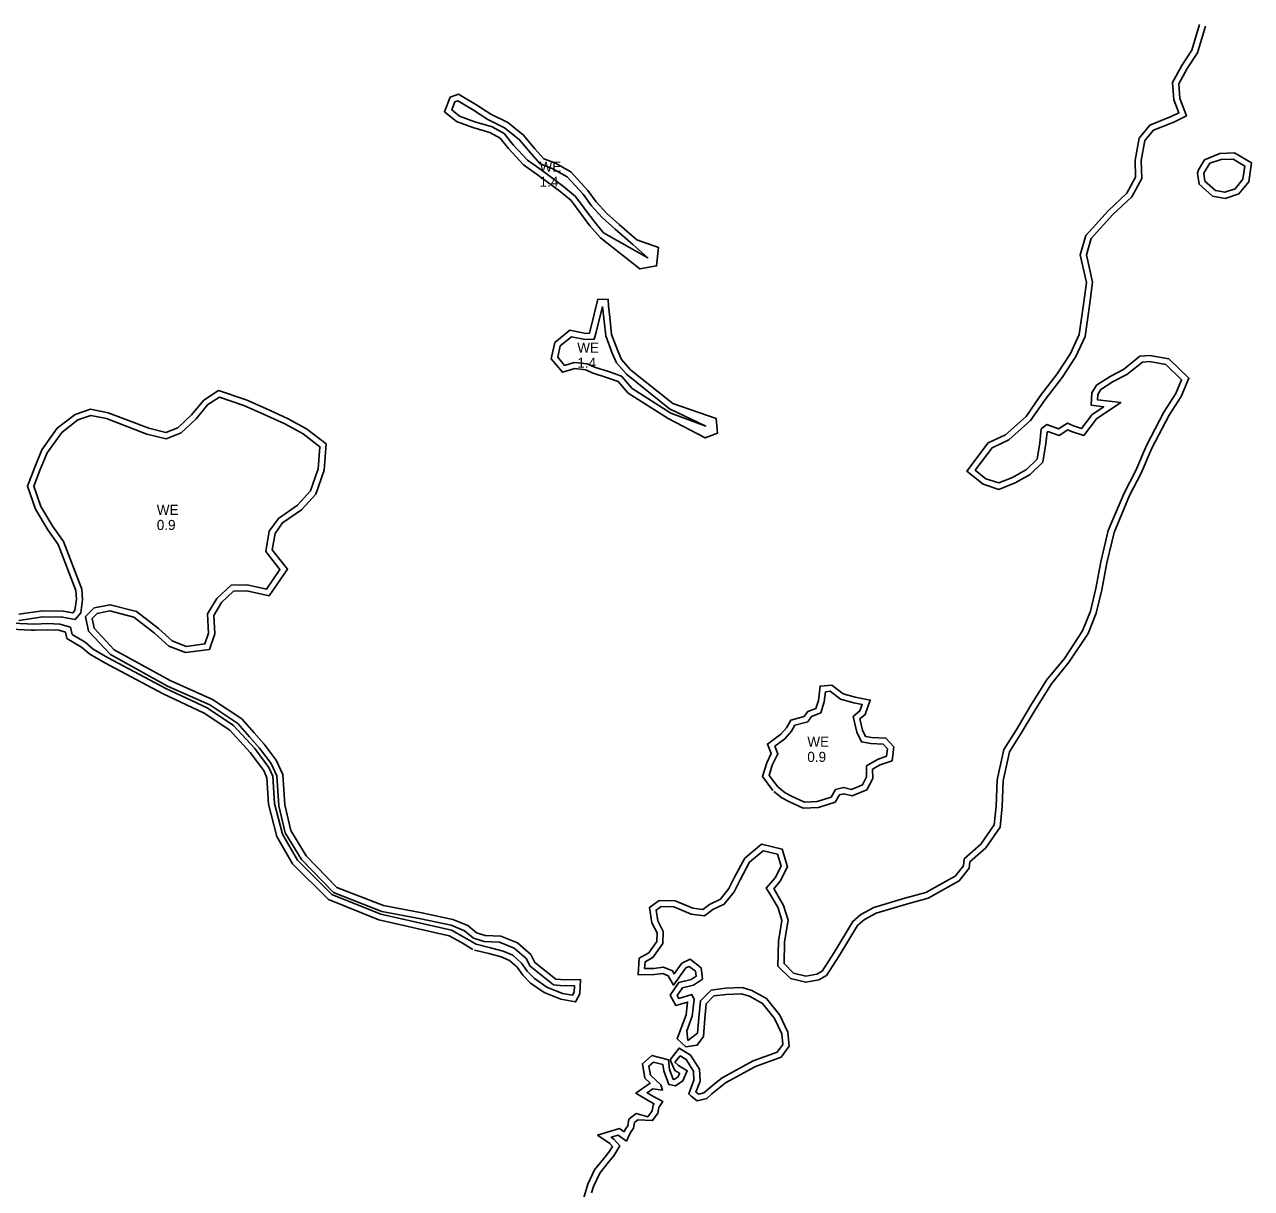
# Model space of a CAD drawing. Extents: x 2160437 to 2172832, y 205694 to 212444.
# Drawn here: x 2167169 to 2167777, y 209235 to 209811 of the extents above; entities that cross this region are included whole.
import ezdxf

# ---------------------------------------------------------------- set-up
doc = ezdxf.new("R2010")
doc.units = 0
for name, color, linetype in [('RD_EX_H2O', 7, 'Continuous'), ('RD_EX_H2O_Pond', 7, 'Continuous'), ('RD_EX_H2O_txCode', 7, 'Continuous'), ('RD_EX_VEG_ShrubLine', 7, 'Continuous')]:
    doc.layers.add(name, color=color, linetype=linetype)

msp = doc.modelspace()

# ---------------------------------------------------------------- linework, layer by layer
at = {"layer": 'RD_EX_H2O'}
for points in [[(2167645.06, 209403.52), (2167652.09, 209413.78), (2167653.08, 209423.92), (2167653.67, 209436.74), (2167656.69, 209451.07), (2167662.59, 209460.23), (2167669.71, 209472.32), (2167677.57, 209484.7), (2167686.36, 209495.54), (2167695.63, 209509.64), (2167699.72, 209519.75), (2167702.49, 209531.33), (2167704.89, 209544.57), (2167708.54, 209559.73), (2167716.18, 209577.94), (2167722.01, 209589.13), (2167727.24, 209601.46), (2167735.77, 209617.77), (2167741.77, 209627.13), (2167745.6, 209636.11), (2167735.59, 209645.64), (2167726.18, 209647.42), (2167721.38, 209646.99), (2167713.19, 209640.49), (2167706.62, 209636.99), (2167699.77, 209632.62), (2167697.48, 209628.93), (2167697.25, 209622.68), (2167703.42, 209621.99), (2167697.67, 209618.12), (2167692.4, 209611.17), (2167688.49, 209612.45), (2167685.39, 209613.86), (2167681.03, 209611.1), (2167675.22, 209613.12), (2167672.5, 209610.99), (2167671.74, 209604.11), (2167670.42, 209595.99), (2167665.13, 209590.91), (2167658.22, 209586.95), (2167651.37, 209584.21), (2167645.09, 209586.31), (2167639.8, 209590.58), (2167648.07, 209601.65), (2167656.46, 209605.57), (2167667.17, 209615.16), (2167674.59, 209625.74), (2167682.83, 209636.46), (2167689.65, 209646.82), (2167694.2, 209656.84), (2167696.58, 209673.33), (2167697.92, 209683.68), (2167694.83, 209697.18), (2167697.27, 209705.29), (2167707.89, 209717.16), (2167717.26, 209725.99), (2167722.21, 209734.96), (2167722.02, 209743.89), (2167723.79, 209753.8), (2167728.01, 209758.99), (2167738.07, 209763.02), (2167744.45, 209766.1), (2167741.09, 209774.61), (2167740.56, 209781.95), (2167744.75, 209789.52), (2167749.89, 209797.28), (2167753.76, 209810.47)], [(2167645.06, 209403.52), (2167637.12, 209396.47), (2167636.78, 209393.38), (2167631.81, 209387.1), (2167616.41, 209378.58), (2167605.78, 209375.62), (2167590.7, 209371.07), (2167584.87, 209367.99), (2167581.48, 209365.04), (2167572.42, 209350.03), (2167566, 209340.17), (2167562.35, 209338.03), (2167555.77, 209336.84), (2167548.16, 209338.74), (2167542.04, 209344.89), (2167542.34, 209357.21), (2167543.99, 209367.43), (2167542.06, 209373.73), (2167537.53, 209381.46), (2167536.26, 209383.46), (2167540.61, 209388.65), (2167543.57, 209394.35), (2167541.73, 209400.3), (2167534.63, 209401.96), (2167527.91, 209396.35), (2167523.24, 209387.57), (2167520.31, 209381.68), (2167515.43, 209375.6), (2167509.69, 209372.85), (2167505.59, 209369.85), (2167499.11, 209370.68), (2167490.43, 209374.19), (2167484.17, 209374.41), (2167481.68, 209372.62), (2167482.48, 209367.27), (2167485.2, 209361.99), (2167484.94, 209356.06), (2167480.06, 209349.18), (2167476.21, 209347), (2167475.98, 209343.62), (2167480.6, 209343.64), (2167485.4, 209344.32), (2167489.78, 209342.46), (2167490.57, 209341.04), (2167494.41, 209346.33), (2167498.53, 209348.26), (2167503.94, 209344), (2167504.71, 209338.42), (2167500.25, 209335.46), (2167494.74, 209334.16), (2167492.17, 209330.28), (2167492.91, 209328.89), (2167499.41, 209330.86), (2167500.46, 209328.38), (2167499.45, 209320.12), (2167496.85, 209312.89), (2167497.39, 209308.03), (2167502.18, 209311.59), (2167502.79, 209319.23), (2167503.61, 209327.64), (2167508.95, 209332.94), (2167516.1, 209333.87), (2167524.29, 209334.2), (2167529.04, 209332.85), (2167536.4, 209328.76), (2167542.9, 209320.57), (2167546.87, 209312.17), (2167547.58, 209305.24), (2167543.58, 209299.71), (2167530.98, 209295.15), (2167516.1, 209287.08), (2167513.34, 209284.84), (2167509.34, 209281.67), (2167506.79, 209279.34), (2167502.08, 209278.18), (2167499.03, 209280.5), (2167497.84, 209281.6), (2167500.43, 209288.4), (2167500.14, 209292.83), (2167496.6, 209298.61), (2167493.66, 209300.38), (2167490.99, 209297.24), (2167492.73, 209295.57), (2167497.06, 209293.04), (2167494.96, 209288.02), (2167491.22, 209285.54), (2167487.89, 209286.3), (2167485.44, 209292.97), (2167485.06, 209296.13), (2167480.32, 209297.34), (2167478.11, 209295.36), (2167478.92, 209290.82), (2167483.99, 209286.08), (2167484.8, 209283.35), (2167480.03, 209284.08), (2167477.21, 209282.12), (2167480.06, 209280.45), (2167484.94, 209277.74), (2167483.09, 209274.9), (2167482.59, 209272.02), (2167479.93, 209268.36), (2167472.68, 209268.73), (2167470.88, 209267.37), (2167470.45, 209264.63), (2167468.98, 209262.5), (2167467.88, 209259.94), (2167466.96, 209258.18), (2167462.94, 209261.13), (2167459.47, 209260.08), (2167460.75, 209259.19), (2167463.75, 209255.78), (2167460.73, 209250.92), (2167458.11, 209247.75), (2167453.74, 209242.38), (2167450.66, 209235.74), (2167449.71, 209232.56)]]:
    msp.add_lwpolyline(points, dxfattribs=at)
msp.add_lwpolyline([(2167753.34, 209744.24), (2167760.99, 209747.37), (2167768.24, 209747.69), (2167776.6, 209742.78), (2167775.22, 209733.43), (2167770.37, 209727.41), (2167763.6, 209725.13), (2167757.36, 209726.22), (2167750.74, 209732.21), (2167749.88, 209737.72), (2167750.33, 209739.26)], close=True, dxfattribs=at)
at = {"layer": 'RD_EX_H2O_Pond'}
for points in [[(2167455.63, 209708.17), (2167451.3, 209713.44), (2167446.57, 209719.64), (2167441.76, 209726.19), (2167435.79, 209731.14), (2167425.16, 209739.02), (2167417.96, 209744.16), (2167410.77, 209751.79), (2167406.35, 209757.41), (2167400.39, 209760.62), (2167391.81, 209763.14), (2167384.32, 209765.98), (2167380.42, 209769.06), (2167381.97, 209773.03), (2167383.45, 209773.54), (2167390.77, 209769.22), (2167398.32, 209764.3), (2167406.62, 209760.22), (2167413.87, 209754.37), (2167419.38, 209747.69), (2167424.27, 209742.29), (2167430.15, 209740), (2167437.59, 209735.93), (2167445.48, 209727.24), (2167449.6, 209721.5), (2167454.94, 209715.71), (2167461.36, 209709.93), (2167470.07, 209702.36), (2167477.55, 209695.66)], [(2167455.12, 209671.65), (2167455.87, 209664.39), (2167456.7, 209657.03), (2167459.94, 209648.52), (2167462.02, 209643.77), (2167466.93, 209638.12), (2167488.26, 209621.01), (2167506.22, 209612.42), (2167489.02, 209618.86), (2167469.76, 209631.04), (2167464.55, 209637.14), (2167458.51, 209639.2), (2167451.08, 209641.64), (2167447.57, 209643.23), (2167441.15, 209643.91), (2167436.33, 209642.48), (2167432.95, 209646.57), (2167434.14, 209652.07), (2167439.71, 209656.65), (2167446.51, 209655.3), (2167450.98, 209655.39), (2167451.91, 209658.96)], [(2167541.95, 209433.72), (2167537.65, 209439.34), (2167539.24, 209444.48), (2167542.03, 209450.07), (2167540.49, 209453.82), (2167545.46, 209457.48), (2167548.72, 209461.24), (2167550.38, 209464.22), (2167556.77, 209465.93), (2167558.7, 209468.54), (2167563.23, 209470.28), (2167564.98, 209475.78), (2167565.58, 209480.8), (2167567.86, 209481.02), (2167572.93, 209477.09), (2167579.63, 209475.24), (2167583.75, 209474.42), (2167582.62, 209471.26), (2167579.29, 209468.6), (2167581.13, 209460.72), (2167583.37, 209455.9), (2167588.12, 209455.11), (2167594.12, 209454.88), (2167596.22, 209452.5), (2167595.79, 209448.82), (2167591.36, 209447.29), (2167585.92, 209444.09), (2167585.97, 209438.58), (2167583.91, 209434.6), (2167578.48, 209432.39), (2167574.56, 209433.36), (2167570.54, 209432.32), (2167568.34, 209428.58), (2167561.49, 209426.4), (2167555.13, 209426.11), (2167548.7, 209429.09), (2167545.54, 209430.78)]]:
    msp.add_lwpolyline(points, close=True, dxfattribs=at)
msp.add_lwpolyline([(2167159.25, 209514.89), (2167173.72, 209514.24), (2167180.33, 209514.54), (2167186.33, 209514.3), (2167191.52, 209512.7), (2167192.42, 209509.18), (2167198.78, 209505.35), (2167202.82, 209501.9), (2167209.95, 209497.72), (2167238.73, 209482.47), (2167259.25, 209472.77), (2167272.37, 209464.07), (2167282.9, 209452.69), (2167289.88, 209443.22), (2167291.84, 209438.91), (2167292.67, 209425.51), (2167296.57, 209410.22), (2167304, 209397.37), (2167321.01, 209380.36), (2167345.24, 209370.6), (2167380.22, 209362.69), (2167386.75, 209359.1), (2167392.46, 209355.76), (2167399.56, 209353.97), (2167405.92, 209352.32), (2167410.69, 209350.22), (2167415.05, 209346.37), (2167417.86, 209342.41), (2167421.45, 209338.79), (2167427.6, 209334.5), (2167435.34, 209331.36), (2167440.22, 209330.45), (2167441.08, 209331.93), (2167441.18, 209335.18), (2167434.12, 209335.28), (2167430.89, 209335.56), (2167419.19, 209344.8), (2167417.22, 209348.68), (2167411.37, 209353.77), (2167404.15, 209356.68), (2167396.42, 209357.07), (2167391.18, 209358.71), (2167386.75, 209362.4), (2167380.13, 209365.1), (2167365.03, 209368.34), (2167345.8, 209371.97), (2167321.87, 209381.28), (2167305.97, 209397.72), (2167297.97, 209410.83), (2167294.69, 209424.34), (2167293.79, 209439.08), (2167290.89, 209445.32), (2167285.12, 209452.92), (2167280.27, 209458.43), (2167274.41, 209465.14), (2167260.54, 209474.37), (2167239.68, 209483.6), (2167211.37, 209499.19), (2167200.53, 209510.85), (2167199.01, 209518.08), (2167203.35, 209522.4), (2167211.19, 209523.89), (2167224.31, 209520.55), (2167235.11, 209512.09), (2167241.92, 209505.95), (2167248.85, 209503.23), (2167258.14, 209504.49), (2167259.97, 209509.89), (2167259.49, 209519.4), (2167264.03, 209526.93), (2167271.07, 209533.51), (2167279.14, 209533.71), (2167288.59, 209531.6), (2167295.33, 209541.37), (2167288.25, 209550.2), (2167290.05, 209560.34), (2167294.52, 209566.6), (2167303.94, 209573.23), (2167310.43, 209580.25), (2167314.21, 209591.18), (2167315.1, 209602.18), (2167306.84, 209608.55), (2167297.77, 209613.54), (2167287.13, 209618.37), (2167277.47, 209622.63), (2167265.34, 209626.65), (2167259.63, 209623.01), (2167253.75, 209615.96), (2167246.35, 209608.98), (2167238.94, 209606.11), (2167229.41, 209608.45), (2167209.32, 209616.08), (2167201.62, 209617.65), (2167195.25, 209615.43), (2167187.19, 209609.19), (2167180.05, 209599.09), (2167176.59, 209590.94), (2167173.38, 209582.62), (2167176.88, 209572.5), (2167182.83, 209562.69), (2167188.06, 209555.14), (2167197.14, 209531.64), (2167197.5, 209526.55), (2167196.64, 209519.84), (2167193.82, 209516.51), (2167187.65, 209517.76), (2167177.92, 209517.88), (2167165.93, 209516.16)], dxfattribs=at)
at = {"layer": 'RD_EX_VEG_ShrubLine'}
for points in [[(2167750.89, 209811.31), (2167747.14, 209798.56), (2167742.18, 209791.08), (2167737.5, 209782.62), (2167738.13, 209773.93), (2167740.64, 209767.59), (2167736.86, 209765.77), (2167726.18, 209761.48), (2167720.97, 209755.09), (2167719.02, 209744.12), (2167719.19, 209735.7), (2167714.86, 209727.85), (2167705.74, 209719.26), (2167694.59, 209706.79), (2167691.73, 209697.28), (2167694.88, 209683.54), (2167693.61, 209673.73), (2167691.29, 209657.69), (2167687.01, 209648.27), (2167680.38, 209638.2), (2167672.17, 209627.52), (2167664.91, 209617.16), (2167654.79, 209608.1), (2167646.12, 209604.05), (2167635.67, 209590.06), (2167643.63, 209583.63), (2167651.46, 209581.01), (2167659.53, 209584.24), (2167666.94, 209588.49), (2167673.22, 209594.51), (2167674.72, 209603.7), (2167675.35, 209609.41), (2167675.78, 209609.75), (2167681.41, 209607.8), (2167685.63, 209610.46), (2167687.4, 209609.65), (2167693.5, 209607.66), (2167699.76, 209615.91), (2167711.88, 209624.07), (2167700.35, 209625.35), (2167700.44, 209628.02), (2167701.96, 209630.46), (2167708.13, 209634.4), (2167714.84, 209637.96), (2167722.54, 209644.08), (2167726.04, 209644.39), (2167734.16, 209642.85), (2167742.02, 209635.37), (2167739.11, 209628.54), (2167733.17, 209619.28), (2167724.52, 209602.74), (2167719.3, 209590.41), (2167713.47, 209579.22), (2167705.68, 209560.67), (2167701.95, 209545.19), (2167699.55, 209531.94), (2167696.86, 209520.67), (2167692.96, 209511.04), (2167683.93, 209497.31), (2167675.13, 209486.46), (2167667.15, 209473.89), (2167660.04, 209461.8), (2167653.87, 209452.23), (2167650.68, 209437.12), (2167650.09, 209424.14), (2167649.18, 209414.84), (2167642.58, 209405.21), (2167634.27, 209397.95), (2167633.89, 209394.57), (2167629.83, 209389.44), (2167615.27, 209381.38), (2167604.95, 209378.51), (2167589.55, 209373.86), (2167583.16, 209370.48), (2167579.15, 209367), (2167569.87, 209351.63), (2167563.88, 209342.4), (2167561.3, 209340.89), (2167555.87, 209339.91), (2167549.7, 209341.45), (2167545.07, 209346.1), (2167545.34, 209356.93), (2167547.07, 209367.64), (2167544.82, 209374.94), (2167540.09, 209383.01), (2167539.97, 209383.21), (2167543.12, 209386.98), (2167546.8, 209394.06), (2167544.08, 209402.82), (2167533.86, 209405.22), (2167525.54, 209398.28), (2167520.57, 209388.95), (2167517.77, 209383.3), (2167513.52, 209378.01), (2167508.15, 209375.44), (2167504.79, 209372.98), (2167499.88, 209373.61), (2167491.06, 209377.17), (2167483.26, 209377.45), (2167478.44, 209373.98), (2167479.59, 209366.33), (2167482.16, 209361.32), (2167481.98, 209357.07), (2167478, 209351.46), (2167473.33, 209348.82), (2167472.77, 209340.6), (2167480.82, 209340.64), (2167484.99, 209341.23), (2167487.66, 209340.1), (2167490.24, 209335.47), (2167496.39, 209343.95), (2167498.12, 209344.76), (2167501.13, 209342.39), (2167501.48, 209339.88), (2167499.04, 209338.26), (2167492.9, 209336.81), (2167488.68, 209330.45), (2167491.41, 209325.3), (2167497.28, 209327.08), (2167496.52, 209320.82), (2167493.8, 209313.25), (2167492.11, 209308.77), (2167496.47, 209304.89), (2167502.06, 209305.63), (2167505.06, 209309.99), (2167505.77, 209318.96), (2167506.49, 209326.27), (2167510.34, 209330.1), (2167516.35, 209330.87), (2167523.93, 209331.18), (2167527.88, 209330.06), (2167534.42, 209326.43), (2167540.33, 209318.98), (2167543.94, 209311.35), (2167544.48, 209306.07), (2167541.69, 209302.21), (2167529.74, 209297.89), (2167514.42, 209289.58), (2167511.46, 209287.18), (2167507.39, 209283.96), (2167505.33, 209282.07), (2167502.76, 209281.43), (2167501.39, 209282.47), (2167503.47, 209287.94), (2167503.09, 209293.76), (2167498.77, 209300.8), (2167493.03, 209304.27), (2167488.63, 209298.45), (2167490.91, 209293.16), (2167493.28, 209291.78), (2167492.55, 209290.01), (2167490.64, 209288.75), (2167490.15, 209288.86), (2167488.37, 209293.67), (2167487.8, 209298.52), (2167479.51, 209300.65), (2167474.87, 209296.48), (2167476.14, 209289.31), (2167478.76, 209286.86), (2167471.64, 209281.91), (2167478.58, 209277.85), (2167480.67, 209276.68), (2167480.24, 209276.03), (2167479.75, 209273.22), (2167477.5, 209270.13), (2167471.74, 209271.78), (2167468.1, 209269.03), (2167467.59, 209265.77), (2167466.34, 209263.95), (2167465.82, 209262.74), (2167463.5, 209264.43), (2167452.68, 209261.17), (2167458.73, 209256.94), (2167460.02, 209255.47), (2167458.29, 209252.67), (2167455.79, 209249.65), (2167451.17, 209243.98), (2167447.85, 209236.81), (2167445.68, 209229.53)], [(2167391.72, 209352.85), (2167398.81, 209351.06), (2167404.93, 209349.48), (2167409.05, 209347.66), (2167412.8, 209344.35), (2167415.56, 209340.47), (2167419.51, 209336.48), (2167426.16, 209331.85), (2167434.49, 209328.47), (2167441.75, 209327.11), (2167443.87, 209331.13), (2167444.28, 209338.14), (2167434.27, 209338.27), (2167432.04, 209338.47), (2167421.57, 209346.74), (2167419.63, 209350.56), (2167412.96, 209356.37), (2167404.81, 209359.65), (2167396.95, 209360.05), (2167392.64, 209361.39), (2167388.31, 209365), (2167381.02, 209367.98), (2167365.62, 209371.28), (2167346.63, 209374.86), (2167323.57, 209383.84), (2167308.36, 209399.57), (2167300.77, 209411.99), (2167297.67, 209424.79), (2167296.75, 209439.83), (2167293.48, 209446.87), (2167287.45, 209454.82), (2167282.53, 209460.41), (2167276.41, 209467.42), (2167261.98, 209477.01), (2167241.01, 209486.29), (2167213.24, 209501.59), (2167203.29, 209512.28), (2167202.28, 209517.1), (2167204.81, 209519.63), (2167211.09, 209520.82), (2167222.96, 209517.79), (2167233.18, 209509.79), (2167240.31, 209503.35), (2167248.48, 209500.16), (2167260.39, 209501.77), (2167263, 209509.47), (2167262.53, 209518.63), (2167266.39, 209525.02), (2167272.29, 209530.54), (2167278.85, 209530.7), (2167289.91, 209528.23), (2167299.07, 209541.51), (2167291.44, 209551.01), (2167292.89, 209559.15), (2167296.66, 209564.44), (2167305.93, 209570.96), (2167313.06, 209578.67), (2167317.17, 209590.56), (2167318.22, 209603.56), (2167308.49, 209611.06), (2167299.11, 209616.22), (2167288.35, 209621.11), (2167278.55, 209625.44), (2167264.93, 209629.95), (2167257.63, 209625.29), (2167251.57, 209618.02), (2167244.72, 209611.57), (2167238.74, 209609.25), (2167230.3, 209611.32), (2167210.16, 209618.97), (2167201.41, 209620.75), (2167193.81, 209618.1), (2167185, 209611.28), (2167177.41, 209600.56), (2167173.81, 209592.07), (2167170.18, 209582.68), (2167174.15, 209571.21), (2167180.31, 209561.06), (2167185.39, 209553.73), (2167194.18, 209530.98), (2167194.49, 209526.64), (2167193.78, 209521.11), (2167192.67, 209519.8), (2167187.97, 209520.75), (2167177.73, 209520.88), (2167165.89, 209519.18)], [(2167158.88, 209511.91), (2167172.1, 209511.31)], [(2167172.1, 209511.31), (2167173.72, 209511.24), (2167180.34, 209511.53), (2167185.82, 209511.32), (2167189.03, 209510.33), (2167189.81, 209507.24), (2167197.02, 209502.91), (2167201.07, 209499.44), (2167208.49, 209495.1), (2167237.39, 209479.79), (2167257.77, 209470.16), (2167270.41, 209461.77), (2167280.58, 209450.77), (2167287.28, 209441.7), (2167288.88, 209438.17), (2167289.69, 209425.04), (2167293.76, 209409.07), (2167301.6, 209395.52), (2167319.32, 209377.8), (2167344.35, 209367.73), (2167379.14, 209359.86), (2167385.27, 209356.49), (2167390.94, 209353.17)], [(2167540.05, 209431.4), (2167543.87, 209428.27), (2167547.36, 209426.41), (2167554.54, 209423.08), (2167562.03, 209423.42), (2167570.35, 209426.07), (2167572.5, 209429.73), (2167574.58, 209430.26), (2167578.71, 209429.24), (2167586.07, 209432.24), (2167588.98, 209437.87), (2167588.94, 209442.38), (2167592.62, 209444.55), (2167598.56, 209446.61), (2167599.35, 209453.48), (2167595.53, 209457.83), (2167588.43, 209458.1), (2167585.42, 209458.6), (2167583.98, 209461.7), (2167582.64, 209467.44), (2167585.16, 209469.45), (2167587.74, 209476.7), (2167580.32, 209478.16), (2167574.3, 209479.83), (2167568.76, 209484.11), (2167562.89, 209483.57), (2167562.04, 209476.42), (2167560.81, 209472.56), (2167556.81, 209471.03), (2167554.98, 209468.55), (2167548.38, 209466.79), (2167546.25, 209462.97), (2167543.41, 209459.7), (2167536.83, 209454.85), (2167538.73, 209450.19), (2167536.44, 209445.6), (2167534.33, 209438.75), (2167539.57, 209431.9)]]:
    msp.add_lwpolyline(points, dxfattribs=at)
for points in [[(2167448.91, 209711.62), (2167454.15, 209705.57), (2167473.63, 209690.28), (2167481.87, 209691.71), (2167482.79, 209700.94), (2167472.05, 209704.61), (2167463.34, 209712.18), (2167457.06, 209717.85), (2167451.93, 209723.4), (2167447.81, 209729.13), (2167439.47, 209738.32), (2167431.42, 209742.72), (2167426.02, 209744.83), (2167421.65, 209749.66), (2167415.99, 209756.51), (2167408.24, 209762.76), (2167399.81, 209766.91), (2167392.36, 209771.77), (2167383.78, 209776.83), (2167379.69, 209775.41), (2167376.82, 209768.09), (2167382.82, 209763.34), (2167390.86, 209760.29), (2167399.24, 209757.83), (2167404.37, 209755.07), (2167408.49, 209749.83), (2167415.98, 209741.89), (2167423.39, 209736.6), (2167433.93, 209728.78), (2167439.56, 209724.11), (2167444.17, 209717.84)], [(2167755.91, 209742.69), (2167761.64, 209744.4), (2167767.48, 209744.66), (2167773.34, 209741.22), (2167772.37, 209734.68), (2167768.58, 209729.98), (2167763.36, 209728.22), (2167758.73, 209729.02), (2167753.54, 209733.73), (2167752.94, 209737.52), (2167753.1, 209738.04)], [(2167458.1, 209671.96), (2167457.98, 209675.15), (2167452.85, 209675.24), (2167451.03, 209667.85), (2167449, 209659.7), (2167448.65, 209658.35), (2167446.77, 209658.31), (2167438.9, 209659.87), (2167431.43, 209653.73), (2167429.71, 209645.78), (2167435.27, 209639.04), (2167441.43, 209640.86), (2167446.77, 209640.3), (2167449.99, 209638.84), (2167457.56, 209636.35), (2167462.81, 209634.56), (2167467.77, 209628.74), (2167487.68, 209616.16), (2167505.99, 209606.55), (2167512.08, 209608.95), (2167511.4, 209616.16), (2167489.87, 209623.57), (2167469.02, 209640.29), (2167464.59, 209645.4), (2167462.72, 209649.66), (2167459.64, 209657.74), (2167458.85, 209664.71)]]:
    msp.add_lwpolyline(points, close=True, dxfattribs=at)

# ---------------------------------------------------------------- texts
at = {"layer": 'RD_EX_H2O_txCode'}
for s, p in [('WE', (2167423.93, 209738.44)), ('1.4', (2167423.93, 209730.94)), ('WE', (2167442.61, 209648.76)), ('1.4', (2167442.61, 209641.26)), ('WE', (2167234.3, 209568.42)), ('0.9', (2167234.3, 209560.92)), ('WE', (2167556.58, 209453.53)), ('0.9', (2167556.58, 209446.03))]:
    msp.add_text(s, height=5, dxfattribs=at).set_placement(p)

doc.saveas('drawing.dxf')
